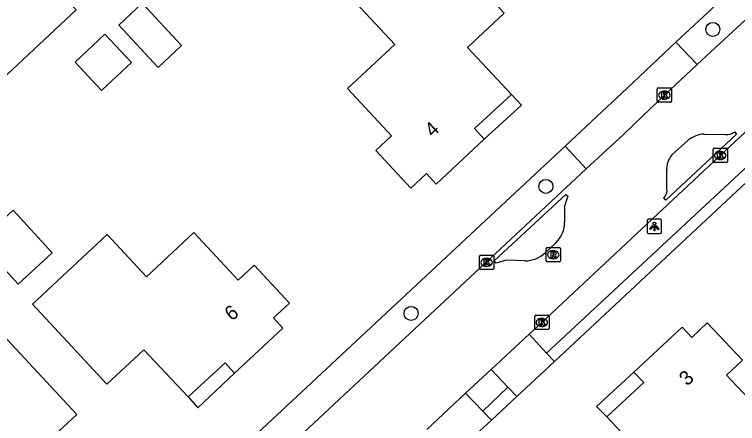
# Model space of a CAD drawing. Extents: x 162675 to 163482, y 379761 to 381227.
# Drawn here: x 163330.7 to 163381.1, y 380877 to 380905.6 of the extents above; entities that cross this region are included whole.
import ezdxf

# ---------------------------------------------------------------- set-up
doc = ezdxf.new("R2010")
doc.units = 0
for name, color, linetype in [('IMGEO_Boom', 7, 'Continuous'), ('IMGEO_Groenvoorziening', 7, 'Continuous'), ('IMGEO_Haag', 7, 'Continuous'), ('IMGEO_Kolk', 7, 'Continuous'), ('IMGEO_Lichtpunt', 7, 'Continuous'), ('IMGEO_Pand', 7, 'Continuous'), ('IMGEO_Pand_nummerreeks', 7, 'Continuous'), ('IMGEO_Pand_overbouw', 7, 'Continuous'), ('IMGEO_Parkeervlak_halfverhard', 7, 'Continuous'), ('IMGEO_Rijbaan_lokaal_gesloten', 7, 'Continuous'), ('IMGEO_Rioolput', 7, 'Continuous'), ('IMGEO_Voetpad_halfverhard', 7, 'Continuous'), ('IMGEO_Voetpad_open', 7, 'Continuous')]:
    doc.layers.add(name, color=color, linetype=linetype)

msp = doc.modelspace()

# ---------------------------------------------------------------- linework, layer by layer
at = {"layer": 'IMGEO_Boom'}
for centre in [(163379.429, 380904.517), (163367.785, 380893.566), (163358.382, 380884.702)]:
    msp.add_circle(centre, 0.489, dxfattribs=at)
at = {"layer": 'IMGEO_Groenvoorziening'}
for points in [[(163376.845, 380903.636), (163390.208, 380916.036)], [(163346.254, 380875.013), (163369.133, 380896.376)]]:
    msp.add_lwpolyline(points, dxfattribs=at)
at = {"layer": 'IMGEO_Haag'}
for points in [[(163388.46, 380900.109), (163368.391, 380881.338)], [(163365.767, 380878.911), (163363.981, 380877.26)]]:
    msp.add_lwpolyline(points, dxfattribs=at)
at = {"layer": 'IMGEO_Kolk'}
for p, q in [((163375.547, 380899.502), (163375.547, 380900.354)), ((163375.622, 380900.428), (163376.474, 380900.428)), ((163376.035, 380900.208), (163376.06, 380900.208)), ((163376.548, 380900.354), (163376.548, 380899.502)), ((163376.058, 380899.648), (163376.033, 380899.648)), ((163376.474, 380899.428), (163375.622, 380899.428)), ((163379.441, 380895.294), (163379.441, 380896.146)), ((163379.516, 380896.22), (163380.368, 380896.22)), ((163380.442, 380896.146), (163380.442, 380895.294)), ((163379.929, 380896), (163379.954, 380896)), ((163380.368, 380895.22), (163379.516, 380895.22)), ((163379.952, 380895.44), (163379.927, 380895.44)), ((163363.146, 380887.833), (163363.146, 380888.685)), ((163363.221, 380888.759), (163364.073, 380888.759)), ((163363.634, 380888.539), (163363.659, 380888.539)), ((163364.147, 380888.685), (163364.147, 380887.833)), ((163363.657, 380887.979), (163363.632, 380887.979)), ((163364.073, 380887.759), (163363.221, 380887.759)), ((163367.001, 380883.643), (163367.001, 380884.495)), ((163367.076, 380884.569), (163367.928, 380884.569)), ((163368.002, 380884.495), (163368.002, 380883.643)), ((163367.489, 380884.349), (163367.514, 380884.349)), ((163367.928, 380883.569), (163367.076, 380883.569)), ((163367.512, 380883.789), (163367.487, 380883.789))]:
    msp.add_line(p, q, dxfattribs=at)
for points in [[(163375.547, 380899.502), (163375.547, 380900.354)], [(163375.622, 380900.428), (163376.474, 380900.428)], [(163375.868, 380900.128), (163375.991, 380900.128), (163375.991, 380899.977), (163376.121, 380900.128), (163376.285, 380900.128), (163376.139, 380899.977), (163376.292, 380899.728), (163376.14, 380899.728), (163376.055, 380899.892), (163375.991, 380899.825), (163375.991, 380899.728), (163375.868, 380899.728), (163375.868, 380900.128)], [(163376.548, 380900.354), (163376.548, 380899.502)], [(163376.474, 380899.428), (163375.622, 380899.428)], [(163379.441, 380895.294), (163379.441, 380896.146)], [(163379.516, 380896.22), (163380.368, 380896.22)], [(163380.442, 380896.146), (163380.442, 380895.294)], [(163379.762, 380895.92), (163379.885, 380895.92), (163379.885, 380895.769), (163380.015, 380895.92), (163380.179, 380895.92), (163380.033, 380895.769), (163380.186, 380895.52), (163380.034, 380895.52), (163379.949, 380895.684), (163379.885, 380895.617), (163379.885, 380895.52), (163379.762, 380895.52), (163379.762, 380895.92)], [(163380.368, 380895.22), (163379.516, 380895.22)], [(163363.146, 380887.833), (163363.146, 380888.685)], [(163363.221, 380888.759), (163364.073, 380888.759)], [(163363.467, 380888.459), (163363.59, 380888.459), (163363.59, 380888.308), (163363.72, 380888.459), (163363.884, 380888.459), (163363.738, 380888.308), (163363.891, 380888.059), (163363.739, 380888.059), (163363.654, 380888.223), (163363.59, 380888.156), (163363.59, 380888.059), (163363.467, 380888.059), (163363.467, 380888.459)], [(163364.147, 380888.685), (163364.147, 380887.833)], [(163364.073, 380887.759), (163363.221, 380887.759)], [(163367.001, 380883.643), (163367.001, 380884.495)], [(163367.076, 380884.569), (163367.928, 380884.569)], [(163368.002, 380884.495), (163368.002, 380883.643)], [(163367.322, 380884.269), (163367.445, 380884.269), (163367.445, 380884.118), (163367.575, 380884.269), (163367.739, 380884.269), (163367.593, 380884.118), (163367.746, 380883.869), (163367.594, 380883.869), (163367.509, 380884.033), (163367.445, 380883.966), (163367.445, 380883.869), (163367.322, 380883.869), (163367.322, 380884.269)], [(163367.928, 380883.569), (163367.076, 380883.569)]]:
    msp.add_lwpolyline(points, dxfattribs=at)
for centre, start, end in [((163375.624, 380900.352), 91.552, 178.448), ((163375.624, 380900.352), 91.552, 178.448), ((163376.472, 380900.352), 1.552, 88.448), ((163376.472, 380900.352), 1.552, 88.448), ((163375.624, 380899.504), 181.552, 268.448), ((163375.624, 380899.504), 181.552, 268.448), ((163376.472, 380899.504), 271.552, 358.448), ((163376.472, 380899.504), 271.552, 358.448), ((163379.518, 380896.144), 91.552, 178.448), ((163379.518, 380896.144), 91.552, 178.448), ((163380.366, 380896.144), 1.552, 88.448), ((163380.366, 380896.144), 1.552, 88.448), ((163379.518, 380895.296), 181.552, 268.448), ((163379.518, 380895.296), 181.552, 268.448), ((163380.366, 380895.296), 271.552, 358.448), ((163380.366, 380895.296), 271.552, 358.448), ((163363.223, 380888.683), 91.552, 178.448), ((163363.223, 380888.683), 91.552, 178.448), ((163364.071, 380888.683), 1.552, 88.448), ((163364.071, 380888.683), 1.552, 88.448), ((163363.223, 380887.835), 181.552, 268.448), ((163363.223, 380887.835), 181.552, 268.448), ((163364.071, 380887.835), 271.552, 358.448), ((163364.071, 380887.835), 271.552, 358.448), ((163367.078, 380884.493), 91.552, 178.448), ((163367.078, 380884.493), 91.552, 178.448), ((163367.926, 380884.493), 1.552, 88.448), ((163367.926, 380884.493), 1.552, 88.448), ((163367.078, 380883.645), 181.552, 268.448), ((163367.078, 380883.645), 181.552, 268.448), ((163367.926, 380883.645), 271.552, 358.448), ((163367.926, 380883.645), 271.552, 358.448)]:
    msp.add_arc(centre, 0.0765, start, end, dxfattribs=at)
for centre, major_axis, ratio, start_param, end_param in [((163376.034, 380899.928), (-0.387, 0.002), 0.722429, 4.712389, 7.853982), ((163376.059, 380899.928), (-0.39, 0.002), 0.717154, 1.570796, 4.712389), ((163379.928, 380895.72), (-0.387, 0.002), 0.722429, 4.712389, 7.853982), ((163379.953, 380895.72), (-0.39, 0.002), 0.717154, 1.570796, 4.712389), ((163363.633, 380888.259), (-0.387, 0.002), 0.722429, 4.712389, 7.853982), ((163363.658, 380888.259), (-0.39, 0.002), 0.717154, 1.570796, 4.712389), ((163367.488, 380884.069), (-0.387, 0.002), 0.722429, 4.712389, 7.853982), ((163367.513, 380884.069), (-0.39, 0.002), 0.717154, 1.570796, 4.712389)]:
    msp.add_ellipse(centre, major_axis=major_axis, ratio=ratio, start_param=start_param, end_param=end_param, dxfattribs=at)
at = {"layer": 'IMGEO_Lichtpunt'}
for p, q in [((163374.851, 380891.17), (163374.851, 380890.363)), ((163374.851, 380891.17), (163374.851, 380890.363)), ((163375.753, 380891.265), (163374.945, 380891.265)), ((163375.753, 380891.265), (163374.945, 380891.265)), ((163375.847, 380890.363), (163375.847, 380891.17)), ((163375.847, 380890.363), (163375.847, 380891.17)), ((163374.945, 380890.269), (163375.753, 380890.269)), ((163374.945, 380890.269), (163375.753, 380890.269))]:
    msp.add_line(p, q, dxfattribs=at)
for points in [[(163375.225, 380890.834), (163375.264, 380890.806), (163375.076, 380890.544), (163375.038, 380890.571), (163375.225, 380890.834)], [(163375.327, 380890.786), (163375.374, 380890.786), (163375.374, 380890.464), (163375.327, 380890.464), (163375.327, 380890.786)], [(163375.437, 380890.806), (163375.475, 380890.833), (163375.662, 380890.571), (163375.623, 380890.543), (163375.437, 380890.806)]]:
    msp.add_lwpolyline(points, dxfattribs=at)
msp.add_circle((163375.35, 380890.968), 0.0994, dxfattribs=at)
for centre, start, end in [((163374.945, 380891.17), 90, 180), ((163374.945, 380891.17), 90, 180), ((163375.753, 380891.17), 0, 90), ((163375.753, 380891.17), 0, 90), ((163374.945, 380890.363), 180, 270), ((163374.945, 380890.363), 180, 270), ((163375.753, 380890.363), 270, 0), ((163375.753, 380890.363), 270, 360)]:
    msp.add_arc(centre, 0.0946, start, end, dxfattribs=at)
at = {"layer": 'IMGEO_Pand'}
for points in [[(163329.836, 380901.028), (163326.546, 380897.941), (163323.815, 380900.853), (163320.728, 380904.144), (163319.628, 380903.111), (163317.164, 380905.738), (163318.266, 380906.772), (163317.581, 380907.499), (163320.931, 380910.641), (163321.617, 380909.914), (163324.172, 380912.316), (163327.25, 380909.035), (163329.806, 380911.425), (163335.008, 380905.88), (163329.836, 380901.028)], [(163359.714, 380911.198), (163364.882, 380905.641), (163362.323, 380903.26), (163365.383, 380899.969), (163362.795, 380897.596), (163363.485, 380896.858), (163360.136, 380893.729), (163359.454, 380894.46), (163358.359, 380893.438), (163355.911, 380896.07), (163357.014, 380897.096), (163353.947, 380900.394), (163357.244, 380903.46), (163354.53, 380906.377), (163359.714, 380911.198)], [(163342.375, 380903.391), (163340.749, 380901.866), (163337.986, 380904.81), (163339.612, 380906.336), (163342.375, 380903.391)], [(163338.871, 380902.215), (163336.787, 380900.26), (163334.943, 380902.227), (163337.027, 380904.182), (163338.871, 380902.215)], [(163333.348, 380888.927), (163330.977, 380886.75), (163328.248, 380889.724), (163330.619, 380891.9), (163333.348, 380888.927)], [(163346.319, 380887.029), (163347.431, 380888.061), (163349.892, 380885.413), (163348.781, 380884.381), (163349.434, 380883.679), (163346.063, 380880.54), (163345.41, 380881.242), (163342.822, 380878.871), (163339.742, 380882.153), (163337.167, 380879.761), (163331.974, 380885.353), (163337.191, 380890.199), (163339.918, 380887.263), (163343.236, 380890.346), (163346.319, 380887.029)], [(163377.756, 380866.3), (163372.568, 380871.824), (163375.112, 380874.212), (163372.04, 380877.482), (163374.604, 380879.872), (163373.921, 380880.604), (163377.285, 380883.752), (163377.968, 380883.021), (163379.03, 380884.046), (163381.486, 380881.429), (163380.388, 380880.398), (163383.466, 380877.119), (163380.187, 380874.04), (163382.91, 380871.14), (163377.756, 380866.3)], [(163335.526, 380872.02), (163333.012, 380869.643), (163333.644, 380868.901), (163330.314, 380865.749), (163329.63, 380866.48), (163328.538, 380865.451), (163326.089, 380868.083), (163327.193, 380869.11), (163324.125, 380872.407), (163327.423, 380875.474), (163324.709, 380878.39), (163329.893, 380883.212), (163335.061, 380877.654), (163332.502, 380875.273), (163335.526, 380872.02)]]:
    msp.add_lwpolyline(points, dxfattribs=at)
at = {"layer": 'IMGEO_Pand_overbouw'}
for points in [[(163365.383, 380899.969), (163362.795, 380897.596), (163363.485, 380896.858), (163366.073, 380899.231)], [(163346.063, 380880.54), (163345.41, 380881.242), (163342.822, 380878.871), (163343.501, 380878.107)], [(163373.921, 380880.604), (163371.322, 380878.212), (163372.04, 380877.482), (163374.604, 380879.872)]]:
    msp.add_lwpolyline(points, close=True, dxfattribs=at)
at = {"layer": 'IMGEO_Parkeervlak_halfverhard'}
msp.add_lwpolyline([(163367.834, 380881.918), (163387.952, 380900.666)], dxfattribs=at)
at = {"layer": 'IMGEO_Rijbaan_lokaal_gesloten'}
for points in [[(163391.687, 380914.45), (163378.343, 380902.059)], [(163386.701, 380902.041), (163375.559, 380891.618), (163367.502, 380884.069), (163366.621, 380883.251)], [(163378.343, 380902.059), (163376.048, 380899.928), (163374.534, 380898.479), (163373.189, 380897.191), (163370.584, 380894.778)], [(163380.937, 380897.361), (163381.074, 380897.218), (163376.151, 380892.613), (163376.012, 380892.755)], [(163378.82, 380897.213), (163380.289, 380897.176)], [(163376.569, 380895.762), (163377.715, 380896.795)], [(163370.584, 380894.778), (163347.737, 380873.443)], [(163376.224, 380893.407), (163376.21, 380894.657)], [(163366.314, 380888.368), (163365.021, 380888.414), (163364.325, 380888.214), (163364.183, 380888.363), (163369.165, 380893.006), (163369.322, 380892.879), (163369.074, 380892.193), (163369.075, 380891.078)], [(163368.471, 380889.631), (163367.749, 380888.95)], [(163363.968, 380880.786), (163366.621, 380883.251)], [(163363.968, 380880.786), (163362.17, 380879.145)], [(163359.467, 380876.598), (163362.17, 380879.145)]]:
    msp.add_lwpolyline(points, dxfattribs=at)
for centre, radius, start, end in [((163378.93, 380895.253), 1.963, 93.2051, 128.2362), ((163380.356, 380898.17), 0.996, 266.1617, 305.7058), ((163377.717, 380894.778), 1.512, 139.4053, 184.5981), ((163375.475, 380893.29), 0.758, 315.1116, 8.8642), ((163367.198, 380891.012), 1.879, 312.6761, 2.0111), ((163366.309, 380890.441), 2.073, 270.1415, 314.0109)]:
    msp.add_arc(centre, radius, start, end, dxfattribs=at)
at = {"layer": 'IMGEO_Rioolput'}
for p, q in [((163367.795, 380888.372), (163367.795, 380889.224)), ((163367.87, 380889.298), (163368.722, 380889.298)), ((163368.283, 380889.078), (163368.308, 380889.078)), ((163368.796, 380889.224), (163368.796, 380888.372)), ((163368.306, 380888.518), (163368.281, 380888.518)), ((163368.722, 380888.298), (163367.87, 380888.298))]:
    msp.add_line(p, q, dxfattribs=at)
for points in [[(163367.795, 380888.372), (163367.795, 380889.224)], [(163367.87, 380889.298), (163368.722, 380889.298)], [(163368.384, 380888.996), (163368.132, 380888.998), (163368.132, 380888.598)], [(163368.796, 380889.224), (163368.796, 380888.372)], [(163368.132, 380888.598), (163368.256, 380888.598), (163368.256, 380888.76), (163368.267, 380888.76)], [(163368.31, 380888.917), (163368.256, 380888.917), (163368.256, 380888.836)], [(163368.256, 380888.836), (163368.308, 380888.836)], [(163368.314, 380888.731), (163368.385, 380888.598), (163368.525, 380888.598), (163368.46, 380888.724)], [(163368.722, 380888.298), (163367.87, 380888.298)]]:
    msp.add_lwpolyline(points, dxfattribs=at)
for centre, radius, start, end in [((163367.872, 380889.222), 0.0765, 91.552, 178.448), ((163367.872, 380889.222), 0.0765, 91.552, 178.448), ((163368.383, 380888.886), 0.109, 350.3612, 89.416), ((163368.72, 380889.222), 0.0765, 1.552, 88.448), ((163368.72, 380889.222), 0.0765, 1.552, 88.448), ((163368.266, 380888.707), 0.0533, 26.0293, 88.6989), ((163368.292, 380889.025), 0.19, 274.7715, 282.9687), ((163368.316, 380888.821), 0.0964, 77.0061, 93.1865), ((163368.33, 380888.878), 0.0378, 276.6634, 79.6772), ((163368.381, 380888.886), 0.112, 277.5842, 350.9817), ((163368.365, 380888.671), 0.108, 29.5134, 73.7905), ((163367.872, 380888.374), 0.0765, 181.552, 268.448), ((163367.872, 380888.374), 0.0765, 181.552, 268.448), ((163368.72, 380888.374), 0.0765, 271.552, 358.448), ((163368.72, 380888.374), 0.0765, 271.552, 358.448)]:
    msp.add_arc(centre, radius, start, end, dxfattribs=at)
for centre, major_axis, ratio, start_param, end_param in [((163368.282, 380888.798), (-0.387, 0.002), 0.722429, 4.712389, 7.853982), ((163368.307, 380888.798), (-0.39, 0.002), 0.717154, 1.570796, 4.712389)]:
    msp.add_ellipse(centre, major_axis=major_axis, ratio=ratio, start_param=start_param, end_param=end_param, dxfattribs=at)
at = {"layer": 'IMGEO_Voetpad_halfverhard'}
msp.add_lwpolyline([(163363.39, 380877.885), (163365.131, 380879.565)], dxfattribs=at)
at = {"layer": 'IMGEO_Voetpad_open'}
for points in [[(163369.133, 380896.376), (163371.715, 380898.787), (163373.061, 380900.044), (163376.845, 380903.636)], [(163378.343, 380902.059), (163376.845, 380903.636)], [(163369.133, 380896.376), (163370.584, 380894.778)], [(163366.621, 380883.251), (163367.834, 380881.918)], [(163368.391, 380881.338), (163367.834, 380881.918)], [(163368.391, 380881.338), (163365.767, 380878.911)], [(163365.131, 380879.565), (163363.968, 380880.786)], [(163365.131, 380879.565), (163365.767, 380878.911)], [(163362.17, 380879.145), (163363.39, 380877.885)], [(163363.981, 380877.26), (163363.39, 380877.885)], [(163363.981, 380877.26), (163361.251, 380874.736)]]:
    msp.add_lwpolyline(points, dxfattribs=at)

# ---------------------------------------------------------------- texts
at = {"layer": 'IMGEO_Pand_nummerreeks'}
for s, rotation, p in [('4', 43.0584, (163359.89, 380896.947)), ('6', 37.0212, (163345.848, 380884.131)), ('3', 43.0977, (163377.643, 380879.595))]:
    msp.add_text(s, height=1, rotation=rotation, dxfattribs=at).set_placement(p)

doc.saveas('drawing.dxf')
